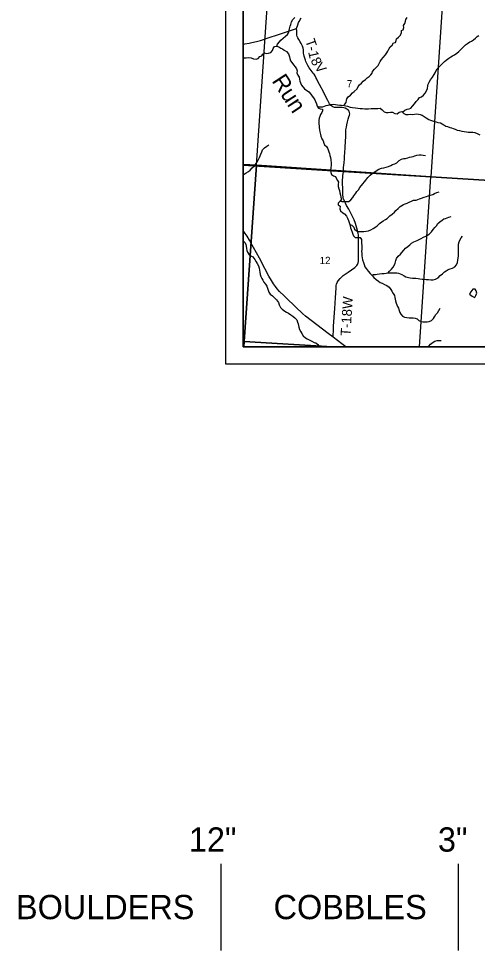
# Model space of a CAD drawing. Extents: x -13.7 to 34, y 0 to 32.3.
# Drawn here: x 22.22 to 24.87, y 10.62 to 16 of the extents above; entities that cross this region are included whole.
import ezdxf

# ---------------------------------------------------------------- set-up
doc = ezdxf.new("R2010")
doc.units = 0
for name, color, linetype in [('GM_X_Corporation', 7, 'Continuous'), ('GM_X_County_Road', 7, 'Continuous'), ('GM_X_Minor_Lake', 7, 'Continuous'), ('GM_X_Minor_River', 7, 'Continuous'), ('GM_X_Minor_River_Text', 7, 'Continuous'), ('GM_X_Section_Text', 7, 'Continuous'), ('GM_X_State_Route', 7, 'Continuous'), ('GM_X_Township_Road', 7, 'Continuous'), ('GM_X_Township_Road_Text', 7, 'Continuous'), ('SH_Data', 7, 'Continuous'), ('SH_Text', 7, 'Continuous')]:
    doc.layers.add(name, color=color, linetype=linetype)

msp = doc.modelspace()

# ---------------------------------------------------------------- linework, layer by layer
at = {"layer": 'GM_X_Corporation'}
for points in [[(23.5167, 20.9), (23.5167, 14.1), (25.5491, 14.1), (25.6174, 15.0182), (25.6502, 15.5943), (25.6733, 15.948), (25.6857, 16.1459)], [(23.5167, 20.9), (23.5167, 15.1495), (24.0951, 15.113), (24.5995, 15.0813), (25.154, 15.0469), (25.6174, 15.0182), (25.6502, 15.5943), (25.6733, 15.948), (25.6857, 16.1459)]]:
    msp.add_lwpolyline(points, dxfattribs=at)
for points in [[(23.5167, 16.1844), (23.5167, 15.154), (23.5939, 15.1496), (23.6639, 16.1752)], [(23.6639, 16.1752), (24.6695, 16.1208), (24.5999, 15.0816), (23.5939, 15.1496)], [(23.5167, 15.154), (23.5167, 14.1329), (23.5222, 14.1326), (23.5939, 15.1496)], [(23.5167, 15.1495), (23.5167, 14.1), (25.5491, 14.1), (25.6174, 15.0182), (25.154, 15.0469), (24.5995, 15.0813), (24.0951, 15.113)], [(24.0321, 14.1), (24.5352, 14.1), (24.5999, 15.0816), (23.5939, 15.1496), (23.5222, 14.1326)], [(23.5167, 14.1329), (23.5167, 14.1), (23.5199, 14.1), (23.5222, 14.1326)], [(23.5199, 14.1), (24.0321, 14.1), (23.5222, 14.1326)]]:
    msp.add_lwpolyline(points, close=True, dxfattribs=at)
at = {"layer": 'GM_X_County_Road'}
msp.add_lwpolyline([(23.5167, 15.8465), (23.5264, 15.849), (23.5522, 15.8544), (23.5678, 15.858), (23.5948, 15.8634), (23.6175, 15.8694), (23.6617, 15.8849), (23.7212, 15.9034), (23.7614, 15.9175), (23.8255, 15.9392), (23.8319, 15.9593), (23.8364, 15.9727), (23.8393, 15.9788), (23.8512, 15.9998)], dxfattribs=at)
at = {"layer": 'GM_X_Minor_Lake'}
for points in [[(24.8423, 14.4333), (24.832, 14.4186), (24.8229, 14.4049), (24.838, 14.3924), (24.8524, 14.3848), (24.856, 14.3904)], [(24.856, 14.3904), (24.8604, 14.3973), (24.8654, 14.4109), (24.8627, 14.4234), (24.8563, 14.4337), (24.8423, 14.4333)]]:
    msp.add_lwpolyline(points, dxfattribs=at)
at = {"layer": 'GM_X_Minor_River'}
for points in [[(23.7108, 15.8364), (23.7149, 15.8482), (23.7262, 15.8619), (23.7346, 15.8714), (23.7482, 15.8824), (23.7611, 15.8934), (23.7724, 15.9044), (23.7792, 15.9139), (23.7822, 15.9268), (23.7841, 15.9371), (23.789, 15.9511), (23.7924, 15.961), (23.7962, 15.9762), (23.8034, 15.9898), (23.8143, 16.0023)], [(24.1755, 15.5909), (24.1804, 15.6031), (24.1879, 15.613), (24.1993, 15.6236), (24.2103, 15.6339), (24.2231, 15.6434), (24.233, 15.6533), (24.2443, 15.662), (24.2541, 15.67), (24.2613, 15.6802), (24.2632, 15.6905), (24.2749, 15.7034), (24.2863, 15.7152), (24.2961, 15.7243), (24.3018, 15.7368), (24.3078, 15.7474), (24.315, 15.7603), (24.3245, 15.771), (24.3381, 15.7861), (24.3457, 15.7972), (24.3525, 15.8078), (24.3574, 15.8192), (24.3657, 15.8321), (24.3763, 15.8423), (24.3838, 15.8549), (24.396, 15.8579), (24.4005, 15.8693), (24.4028, 15.8792), (24.4145, 15.889), (24.4258, 15.9004), (24.4304, 15.9148), (24.4303, 15.9277), (24.4402, 15.9315), (24.4447, 15.9444), (24.4432, 15.9562), (24.45, 15.9676), (24.4549, 15.9805), (24.4568, 15.9907), (24.4628, 16.001)], [(24.5812, 15.5917), (24.5838, 15.6075), (24.5857, 15.6174), (24.5913, 15.6284), (24.5985, 15.6424), (24.6095, 15.6568), (24.6193, 15.672), (24.625, 15.683), (24.6288, 15.6929), (24.6363, 15.7046), (24.645, 15.7141), (24.6552, 15.724), (24.6688, 15.7373), (24.6787, 15.7472), (24.6889, 15.7548), (24.704, 15.7669), (24.715, 15.7745), (24.7256, 15.7802), (24.7362, 15.7863), (24.7495, 15.7954), (24.7627, 15.8065), (24.779, 15.8228), (24.7911, 15.8342), (24.8013, 15.8437), (24.8123, 15.8524), (24.8255, 15.8615), (24.8357, 15.8661), (24.846, 15.8726), (24.8577, 15.8824), (24.8679, 15.8912), (24.8781, 15.898)], [(23.5167, 15.7678), (23.5207, 15.7695), (23.5343, 15.7684), (23.5487, 15.771), (23.5631, 15.7692), (23.5771, 15.7639), (23.5915, 15.7605), (23.6036, 15.7654), (23.6127, 15.7764), (23.6256, 15.7806), (23.6305, 15.7909), (23.6403, 15.7977), (23.6502, 15.7943), (23.6623, 15.7951), (23.6767, 15.7993), (23.6862, 15.811), (23.6892, 15.8224), (23.6982, 15.8349), (23.7111, 15.8365), (23.7236, 15.8319), (23.7342, 15.8255), (23.7437, 15.8202), (23.7543, 15.8138), (23.768, 15.8055), (23.779, 15.7918), (23.7835, 15.7751), (23.7862, 15.7645), (23.7893, 15.752), (23.7972, 15.7418), (23.8071, 15.7285), (23.817, 15.7168), (23.8257, 15.7047), (23.8291, 15.6948), (23.8276, 15.6815), (23.8325, 15.6683), (23.8405, 15.6565), (23.8424, 15.6467), (23.8447, 15.6338), (23.8481, 15.6243), (23.8542, 15.6107), (23.8705, 15.5902)], [(23.8705, 15.5902), (23.8957, 15.5718), (23.9074, 15.5585), (23.9154, 15.5479), (23.9222, 15.5384), (23.9305, 15.5266), (23.9354, 15.5171), (23.9399, 15.5031), (23.9444, 15.4909), (23.9516, 15.478), (23.9618, 15.4754), (23.9743, 15.4727), (23.9751, 15.4632), (23.9716, 15.4537), (23.9636, 15.442), (23.9591, 15.4295), (23.9556, 15.42), (23.9537, 15.4067), (23.9537, 15.3969), (23.9544, 15.387), (23.9548, 15.3771), (23.9559, 15.3677), (23.9574, 15.3532), (23.9593, 15.3419), (23.963, 15.3263), (23.9653, 15.3161), (23.9717, 15.3024), (23.9785, 15.2891), (23.9819, 15.277), (23.9856, 15.2675), (23.997, 15.2568), (24.0038, 15.2469), (24.0083, 15.2371), (24.0117, 15.2268), (24.0147, 15.2166), (24.0166, 15.206), (24.0211, 15.1938), (24.0237, 15.1798), (24.0252, 15.1601), (24.0244, 15.1502), (24.0221, 15.1346), (24.0213, 15.121), (24.0221, 15.107), (24.0277, 15.0948), (24.0376, 15.0883), (24.0508, 15.0845), (24.0546, 15.0735), (24.0617, 15.0617), (24.0667, 15.0523), (24.0662, 15.0397), (24.0655, 15.0257), (24.0696, 15.0124), (24.0734, 15.0029), (24.0749, 14.9889), (24.0779, 14.9756), (24.0816, 14.9657), (24.0843, 14.9525), (24.0755, 14.94), (24.066, 14.9301), (24.0649, 14.9203), (24.0762, 14.9119), (24.0747, 14.8982), (24.0781, 14.8857), (24.0913, 14.8751), (24.1015, 14.8682), (24.114, 14.8549), (24.1193, 14.8439), (24.1249, 14.8306), (24.1306, 14.8132), (24.134, 14.8014), (24.1373, 14.7878), (24.1403, 14.7783), (24.1456, 14.7631), (24.1498, 14.7517), (24.1531, 14.7411), (24.1637, 14.732), (24.1777, 14.7323), (24.1914, 14.7323), (24.2001, 14.7197), (24.2008, 14.7087), (24.2008, 14.6977), (24.2011, 14.6875), (24.2023, 14.6773), (24.2026, 14.6632), (24.2007, 14.6537), (24.201, 14.6393), (24.2025, 14.6261), (24.2044, 14.6143), (24.2067, 14.6022), (24.2112, 14.5885), (24.2146, 14.576), (24.2202, 14.5631), (24.2274, 14.5524), (24.2383, 14.5384), (24.2493, 14.5251), (24.261, 14.5122), (24.272, 14.5015), (24.2848, 14.4894), (24.2981, 14.4791), (24.3083, 14.4715), (24.3189, 14.4677)], [(24.0953, 15.4935), (24.1035, 15.502), (24.1115, 15.5119), (24.1134, 15.5221), (24.1157, 15.532), (24.1237, 15.5437), (24.1362, 15.5539), (24.1484, 15.5664), (24.1579, 15.5744), (24.1755, 15.5909)], [(24.4371, 15.455), (24.4497, 15.4673), (24.463, 15.4733), (24.4751, 15.4748), (24.4846, 15.4793), (24.4948, 15.4892), (24.5058, 15.5028), (24.5153, 15.5172), (24.5263, 15.5293), (24.5343, 15.5396), (24.5464, 15.5448), (24.5582, 15.5528), (24.5669, 15.5657), (24.5757, 15.5789), (24.5812, 15.5917)], [(23.9474, 15.4855), (23.9577, 15.486), (23.9671, 15.4864), (23.977, 15.4871), (23.9865, 15.4894), (23.9967, 15.4935), (24.0077, 15.4965), (24.0217, 15.4995), (24.0365, 15.5006), (24.0494, 15.4995), (24.0615, 15.4972), (24.0747, 15.496), (24.0846, 15.4949), (24.0997, 15.4929), (24.1096, 15.491), (24.1194, 15.4899), (24.1346, 15.4842), (24.1486, 15.4818), (24.1649, 15.4795), (24.1781, 15.4784), (24.1914, 15.4765), (24.2058, 15.4757), (24.2202, 15.4741), (24.2315, 15.4753), (24.241, 15.4752), (24.2554, 15.4763), (24.2683, 15.4771), (24.2952, 15.477), (24.3084, 15.4793), (24.3201, 15.4694), (24.3311, 15.4572), (24.3425, 15.4534), (24.3542, 15.4542), (24.3675, 15.4545), (24.3796, 15.4549), (24.3932, 15.4484), (24.4057, 15.4461), (24.4182, 15.4556), (24.433, 15.459), (24.4451, 15.4472), (24.4564, 15.4415), (24.4697, 15.4418), (24.483, 15.4429), (24.4962, 15.4425), (24.5068, 15.4429), (24.5163, 15.4451), (24.5296, 15.4436), (24.5394, 15.4424), (24.5511, 15.4383), (24.5617, 15.4306), (24.5742, 15.4227), (24.589, 15.4139), (24.5992, 15.4093), (24.6098, 15.4059), (24.6208, 15.4013), (24.6306, 15.3987), (24.6416, 15.396), (24.656, 15.3933), (24.6658, 15.3884), (24.6756, 15.3819), (24.6862, 15.375), (24.6961, 15.372), (24.709, 15.3674), (24.7188, 15.364), (24.7294, 15.3606), (24.74, 15.3567), (24.7529, 15.3518), (24.7665, 15.3487), (24.779, 15.3461), (24.7926, 15.3434), (24.8059, 15.3411), (24.8157, 15.3403), (24.8278, 15.3391), (24.8418, 15.3399), (24.8547, 15.3376), (24.8672, 15.3326), (24.8823, 15.3246)], [(23.5167, 15.0946), (23.522, 15.098), (23.5349, 15.1056), (23.5475, 15.1131), (23.5573, 15.1215), (23.5687, 15.1332), (23.582, 15.1453), (23.5922, 15.1589), (23.5983, 15.1688), (23.6063, 15.1817), (23.6105, 15.1938), (23.6143, 15.2037), (23.6181, 15.2131), (23.6253, 15.2264), (23.6284, 15.2382), (23.6402, 15.2488), (23.653, 15.2582), (23.6659, 15.2665)], [(24.0783, 14.9439), (24.0869, 14.9403), (24.1009, 14.9399), (24.1141, 14.9391), (24.127, 14.9403), (24.1388, 14.9493), (24.1506, 14.9626), (24.1563, 14.9728), (24.1677, 14.9883), (24.173, 14.9978), (24.1821, 15.0077), (24.1912, 15.0205), (24.2072, 15.041), (24.2182, 15.0539), (24.2254, 15.0637), (24.2368, 15.0777), (24.2493, 15.0917), (24.2618, 15.102), (24.2766, 15.111), (24.2906, 15.1201), (24.3005, 15.1258), (24.3149, 15.1315), (24.3286, 15.1337), (24.343, 15.1371), (24.3555, 15.1424), (24.3687, 15.1477), (24.3794, 15.1526), (24.3919, 15.1567), (24.4036, 15.1635), (24.4169, 15.1756), (24.4317, 15.1832), (24.4446, 15.1885), (24.454, 15.1889), (24.4684, 15.1919), (24.4779, 15.1949), (24.4882, 15.1968), (24.4976, 15.2002), (24.5086, 15.2039), (24.5185, 15.2081), (24.5321, 15.2096), (24.545, 15.2095), (24.5556, 15.2076), (24.5696, 15.2057)], [(24.1326, 14.8061), (24.1438, 14.8029), (24.1551, 14.7919), (24.16, 14.7797), (24.1718, 14.7706), (24.1854, 14.7664), (24.2009, 14.7664), (24.2127, 14.7668), (24.2263, 14.7679), (24.2396, 14.7705), (24.254, 14.7758), (24.2665, 14.783), (24.2779, 14.7905), (24.29, 14.7985), (24.3044, 14.8121), (24.3166, 14.8231), (24.326, 14.8288), (24.3393, 14.8359), (24.3488, 14.8424), (24.3636, 14.8564), (24.3765, 14.8662), (24.3902, 14.8783), (24.3985, 14.8886), (24.4114, 14.9003), (24.4228, 14.9109), (24.4327, 14.9166), (24.4429, 14.9222), (24.4524, 14.9268), (24.463, 14.9305), (24.4744, 14.9358), (24.4888, 14.9422), (24.5002, 14.9468), (24.5149, 14.9479), (24.5259, 14.9505), (24.5354, 14.9543), (24.5468, 14.9584), (24.5619, 14.9649), (24.5752, 14.9686), (24.5847, 14.9717), (24.5987, 14.9758), (24.6112, 14.9811), (24.6218, 14.9864), (24.6351, 14.992), (24.648, 14.9958)], [(24.3542, 14.5287), (24.3622, 14.5374), (24.374, 14.5484), (24.3823, 14.5609), (24.3907, 14.5745), (24.3937, 14.5847), (24.3983, 14.5995), (24.4029, 14.6098), (24.4109, 14.6234), (24.4253, 14.6363), (24.4333, 14.6461), (24.4446, 14.6594), (24.4541, 14.6696), (24.4682, 14.6802), (24.4792, 14.69), (24.4894, 14.6995), (24.5019, 14.7071), (24.5114, 14.7112), (24.5213, 14.7154), (24.5334, 14.7207), (24.544, 14.7259), (24.5581, 14.7339), (24.5706, 14.7396), (24.5914, 14.752), (24.6043, 14.7641), (24.6134, 14.7774), (24.6229, 14.7891), (24.632, 14.799), (24.6412, 14.8119), (24.6518, 14.8217), (24.6655, 14.8327), (24.6749, 14.8395), (24.6844, 14.8418), (24.6943, 14.8463), (24.7037, 14.8497), (24.7174, 14.8535)], [(24.2588, 14.5146), (24.2694, 14.5175), (24.2807, 14.5186), (24.2906, 14.5212), (24.3046, 14.5231), (24.3179, 14.5242), (24.33, 14.5246), (24.3425, 14.5253), (24.3542, 14.5287), (24.3679, 14.5283), (24.3777, 14.5279), (24.3936, 14.5282), (24.4035, 14.5275), (24.4133, 14.5259), (24.4235, 14.5229), (24.4334, 14.5183), (24.4462, 14.5103), (24.4568, 14.5046), (24.4705, 14.5012), (24.4803, 14.4996), (24.4936, 14.4977), (24.5034, 14.4973), (24.5133, 14.4965), (24.5273, 14.4957), (24.5375, 14.4942), (24.5511, 14.4923), (24.5636, 14.4907), (24.5735, 14.4896), (24.5867, 14.4888), (24.5996, 14.4873), (24.6129, 14.4869), (24.6273, 14.491), (24.6421, 14.4989), (24.655, 14.5118), (24.6667, 14.5217), (24.6785, 14.533), (24.688, 14.5398), (24.7009, 14.5463), (24.7122, 14.5504), (24.7251, 14.5549), (24.7388, 14.5621), (24.7483, 14.5742), (24.7543, 14.5867), (24.7566, 14.6008), (24.7586, 14.6137), (24.7593, 14.6235), (24.7597, 14.633), (24.7594, 14.6463), (24.759, 14.6603), (24.7594, 14.6717), (24.7591, 14.6842), (24.7602, 14.6937), (24.7633, 14.7073), (24.7667, 14.7172), (24.7751, 14.7293), (24.7827, 14.7395)], [(23.5167, 14.7113), (23.5179, 14.7104), (23.5281, 14.7009), (23.5326, 14.6914), (23.5348, 14.6811), (23.5363, 14.6679), (23.5382, 14.6576), (23.542, 14.6477), (23.5491, 14.636), (23.562, 14.6257), (23.5718, 14.62), (23.5839, 14.6059), (23.5926, 14.5911), (23.5979, 14.5816), (23.6058, 14.568), (23.6092, 14.5543), (23.6111, 14.5437), (23.613, 14.5319), (23.6152, 14.519), (23.6193, 14.5073), (23.6246, 14.4955), (23.6299, 14.4849), (23.6367, 14.4735), (23.6465, 14.4628), (23.6526, 14.4514), (23.6571, 14.4401), (23.6605, 14.4279), (23.665, 14.4173), (23.6725, 14.404), (23.6862, 14.3956), (23.6983, 14.3846), (23.71, 14.3713), (23.7202, 14.3565), (23.7255, 14.3428), (23.7322, 14.3273), (23.7428, 14.3174), (23.7572, 14.3075)], [(24.3189, 14.4677), (24.3325, 14.4612), (24.3465, 14.454), (24.3594, 14.4452), (24.3692, 14.4323), (24.3756, 14.4217), (24.3835, 14.4084), (24.3896, 14.3978), (24.3933, 14.3864), (24.3948, 14.3769), (24.3967, 14.367), (24.4005, 14.3537), (24.4046, 14.3435), (24.4084, 14.334), (24.4133, 14.3238), (24.4171, 14.3105), (24.4204, 14.2983), (24.4261, 14.2885), (24.4363, 14.2782), (24.4488, 14.2729), (24.4624, 14.2706), (24.4757, 14.269), (24.4874, 14.2682), (24.4976, 14.2675), (24.5101, 14.2659), (24.5207, 14.2617), (24.5306, 14.2534), (24.545, 14.248), (24.5548, 14.2461), (24.5662, 14.245), (24.5783, 14.2457), (24.5912, 14.2476), (24.6044, 14.2532), (24.6162, 14.2638), (24.6208, 14.2737), (24.6291, 14.2869), (24.6382, 14.2972), (24.6455, 14.3108), (24.6542, 14.3241)], [(23.7572, 14.3075), (23.767, 14.3014), (23.778, 14.2946), (23.7916, 14.2862), (23.8037, 14.2782), (23.8155, 14.2683), (23.826, 14.2562), (23.8306, 14.2436), (23.8336, 14.2342), (23.8354, 14.2247), (23.8373, 14.2144), (23.8426, 14.2015), (23.8498, 14.1882), (23.8547, 14.178), (23.863, 14.1647), (23.8762, 14.1529), (23.8864, 14.1468), (23.8978, 14.1404), (23.9129, 14.1327), (23.9265, 14.1266), (23.9371, 14.124), (23.9473, 14.1148), (23.9579, 14.1008), (23.9585, 14.1)], [(24.5833, 14.1), (24.5878, 14.105), (24.5981, 14.1171), (24.6129, 14.1284), (24.6228, 14.133), (24.636, 14.1367), (24.6459, 14.1375), (24.6591, 14.1374)]]:
    msp.add_lwpolyline(points, dxfattribs=at)
at = {"layer": 'GM_X_State_Route'}
msp.add_lwpolyline([(24.1097, 14.1), (24.0866, 14.1181), (24.0358, 14.1566), (24.0078, 14.1778), (23.9744, 14.2029), (23.876, 14.2787), (23.8599, 14.2934), (23.8206, 14.3308), (23.7631, 14.3848), (23.7528, 14.3956), (23.7269, 14.4207), (23.7135, 14.4351), (23.7034, 14.4488), (23.6928, 14.4644), (23.6801, 14.4841), (23.6657, 14.5097), (23.6425, 14.5531), (23.6105, 14.6124), (23.5772, 14.6736), (23.5698, 14.6868), (23.5534, 14.7172), (23.5399, 14.7405), (23.529, 14.7558), (23.5167, 14.7721)], dxfattribs=at)
at = {"layer": 'GM_X_Township_Road'}
for points in [[(24.0953, 15.1125), (24.0969, 15.1363), (24.0993, 15.1625), (24.1017, 15.1855), (24.1026, 15.2049), (24.1035, 15.2177), (24.1058, 15.2561), (24.1089, 15.3153), (24.1091, 15.3314), (24.1104, 15.3526), (24.1127, 15.3682), (24.1154, 15.3819), (24.1184, 15.3996), (24.1224, 15.4156), (24.127, 15.4288), (24.1298, 15.4377), (24.1319, 15.4449), (24.1315, 15.4539), (24.129, 15.4613), (24.1227, 15.4683), (24.1154, 15.4736), (24.1065, 15.4777), (24.0979, 15.4803), (24.0887, 15.4817), (24.0563, 15.4814), (24.0439, 15.4826), (24.035, 15.4854), (24.0282, 15.49), (24.0215, 15.4966), (24.0149, 15.5039), (24.0055, 15.5226), (23.9965, 15.5398), (23.9819, 15.5682), (23.9572, 15.6159), (23.9466, 15.6355), (23.9422, 15.6453), (23.937, 15.6562), (23.9316, 15.6648), (23.9258, 15.674), (23.9206, 15.6812), (23.9158, 15.6877), (23.9089, 15.6955), (23.9034, 15.7031), (23.8982, 15.7108), (23.8907, 15.7249), (23.885, 15.7361), (23.8795, 15.7485), (23.8773, 15.7556), (23.8689, 15.7795), (23.8666, 15.7875), (23.8654, 15.7959), (23.8658, 15.8056), (23.8654, 15.8149), (23.8634, 15.8257), (23.8588, 15.8367), (23.8511, 15.8514), (23.8454, 15.8608), (23.8373, 15.8746), (23.8319, 15.8847), (23.8283, 15.8929), (23.8264, 15.9001), (23.8262, 15.9091), (23.8258, 15.9241), (23.8255, 15.9392)], [(24.0358, 14.1566), (24.0368, 14.1668), (24.0382, 14.197), (24.0387, 14.2118), (24.0393, 14.2197), (24.0466, 14.3215), (24.0499, 14.3833), (24.0535, 14.442), (24.0546, 14.454), (24.0563, 14.463), (24.0591, 14.4713), (24.0661, 14.4824), (24.0772, 14.4959), (24.094, 14.5118), (24.1224, 14.5319), (24.1414, 14.5454), (24.1607, 14.5595), (24.1733, 14.5697), (24.1776, 14.5761), (24.181, 14.5853), (24.1824, 14.596), (24.1825, 14.6075), (24.1831, 14.6193), (24.1828, 14.6454), (24.183, 14.7066), (24.1831, 14.7452), (24.1811, 14.7575), (24.1736, 14.786), (24.1649, 14.8129), (24.1574, 14.8337), (24.1439, 14.8612), (24.1262, 14.8949), (24.1141, 14.9168), (24.0993, 14.9471), (24.0969, 14.9544), (24.0948, 14.9635), (24.0927, 14.9803), (24.0931, 14.9912), (24.0931, 15.0101), (24.0919, 15.0205), (24.09, 15.0388), (24.0894, 15.0549), (24.093, 15.0877), (24.0953, 15.1125)]]:
    msp.add_lwpolyline(points, dxfattribs=at)
at = {"layer": 'SH_Data'}
for p, q in [((23.3896, 10.6173), (23.3896, 11.1173)), ((24.7596, 10.6173), (24.7596, 11.1173))]:
    msp.add_line(p, q, dxfattribs=at)
for points in [[(23.4167, 21), (30.4167, 21), (30.4167, 14), (23.4167, 14)], [(23.5167, 20.9), (30.3167, 20.9), (30.3167, 14.1), (23.5167, 14.1)]]:
    msp.add_lwpolyline(points, close=True, dxfattribs=at)

# ---------------------------------------------------------------- texts
at = {"layer": 'GM_X_Minor_River_Text'}
msp.add_text('Run', height=0.09471, rotation=303.146, dxfattribs=at).set_placement((23.6791, 15.6359))
at = {"layer": 'GM_X_Section_Text'}
for s, height, p in [('7', 0.0419, (24.1157, 15.5988)), ('12', 0.04186, (23.9586, 14.5785))]:
    msp.add_text(s, height=height, rotation=0, dxfattribs=at).set_placement(p)
at = {"layer": 'GM_X_Township_Road_Text'}
for s, height, rotation, p in [('T', 0.0568, 289.3966, (23.8743, 15.8678)), ('-', 0.0568, 278.1034, (23.8876, 15.8307)), ('1', 0.0568, 282.4646, (23.8918, 15.8032)), ('8', 0.0568, 296.9379, (23.9045, 15.7546)), ('V', 0.0568, 306.3207, (23.9256, 15.715)), ('T-18W', 0.05682, 86.2906, (24.1354, 14.1616))]:
    msp.add_text(s, height=height, rotation=rotation, dxfattribs=at).set_placement(p)
at = {"layer": 'SH_Text'}
for s, p in [('12"', (23.2034, 11.1873)), ('3"', (24.6411, 11.1873)), ('BOULDERS', (22.2054, 10.7973)), ('COBBLES', (23.6923, 10.7973))]:
    msp.add_text(s, height=0.14, dxfattribs=at).set_placement(p)

doc.saveas('drawing.dxf')
